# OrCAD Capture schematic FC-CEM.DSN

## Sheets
1 INDEX: title: INDEX; rev: 1.0; note: 8000084000
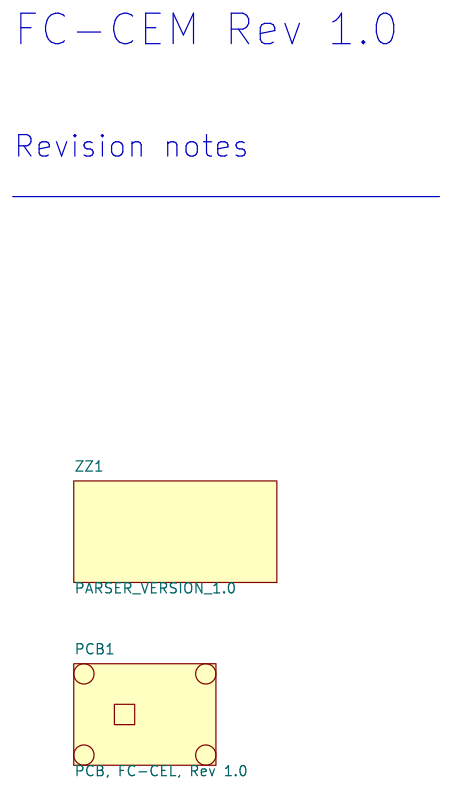
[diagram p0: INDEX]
2 M.2 SATA: size B; title: M.2 SATA
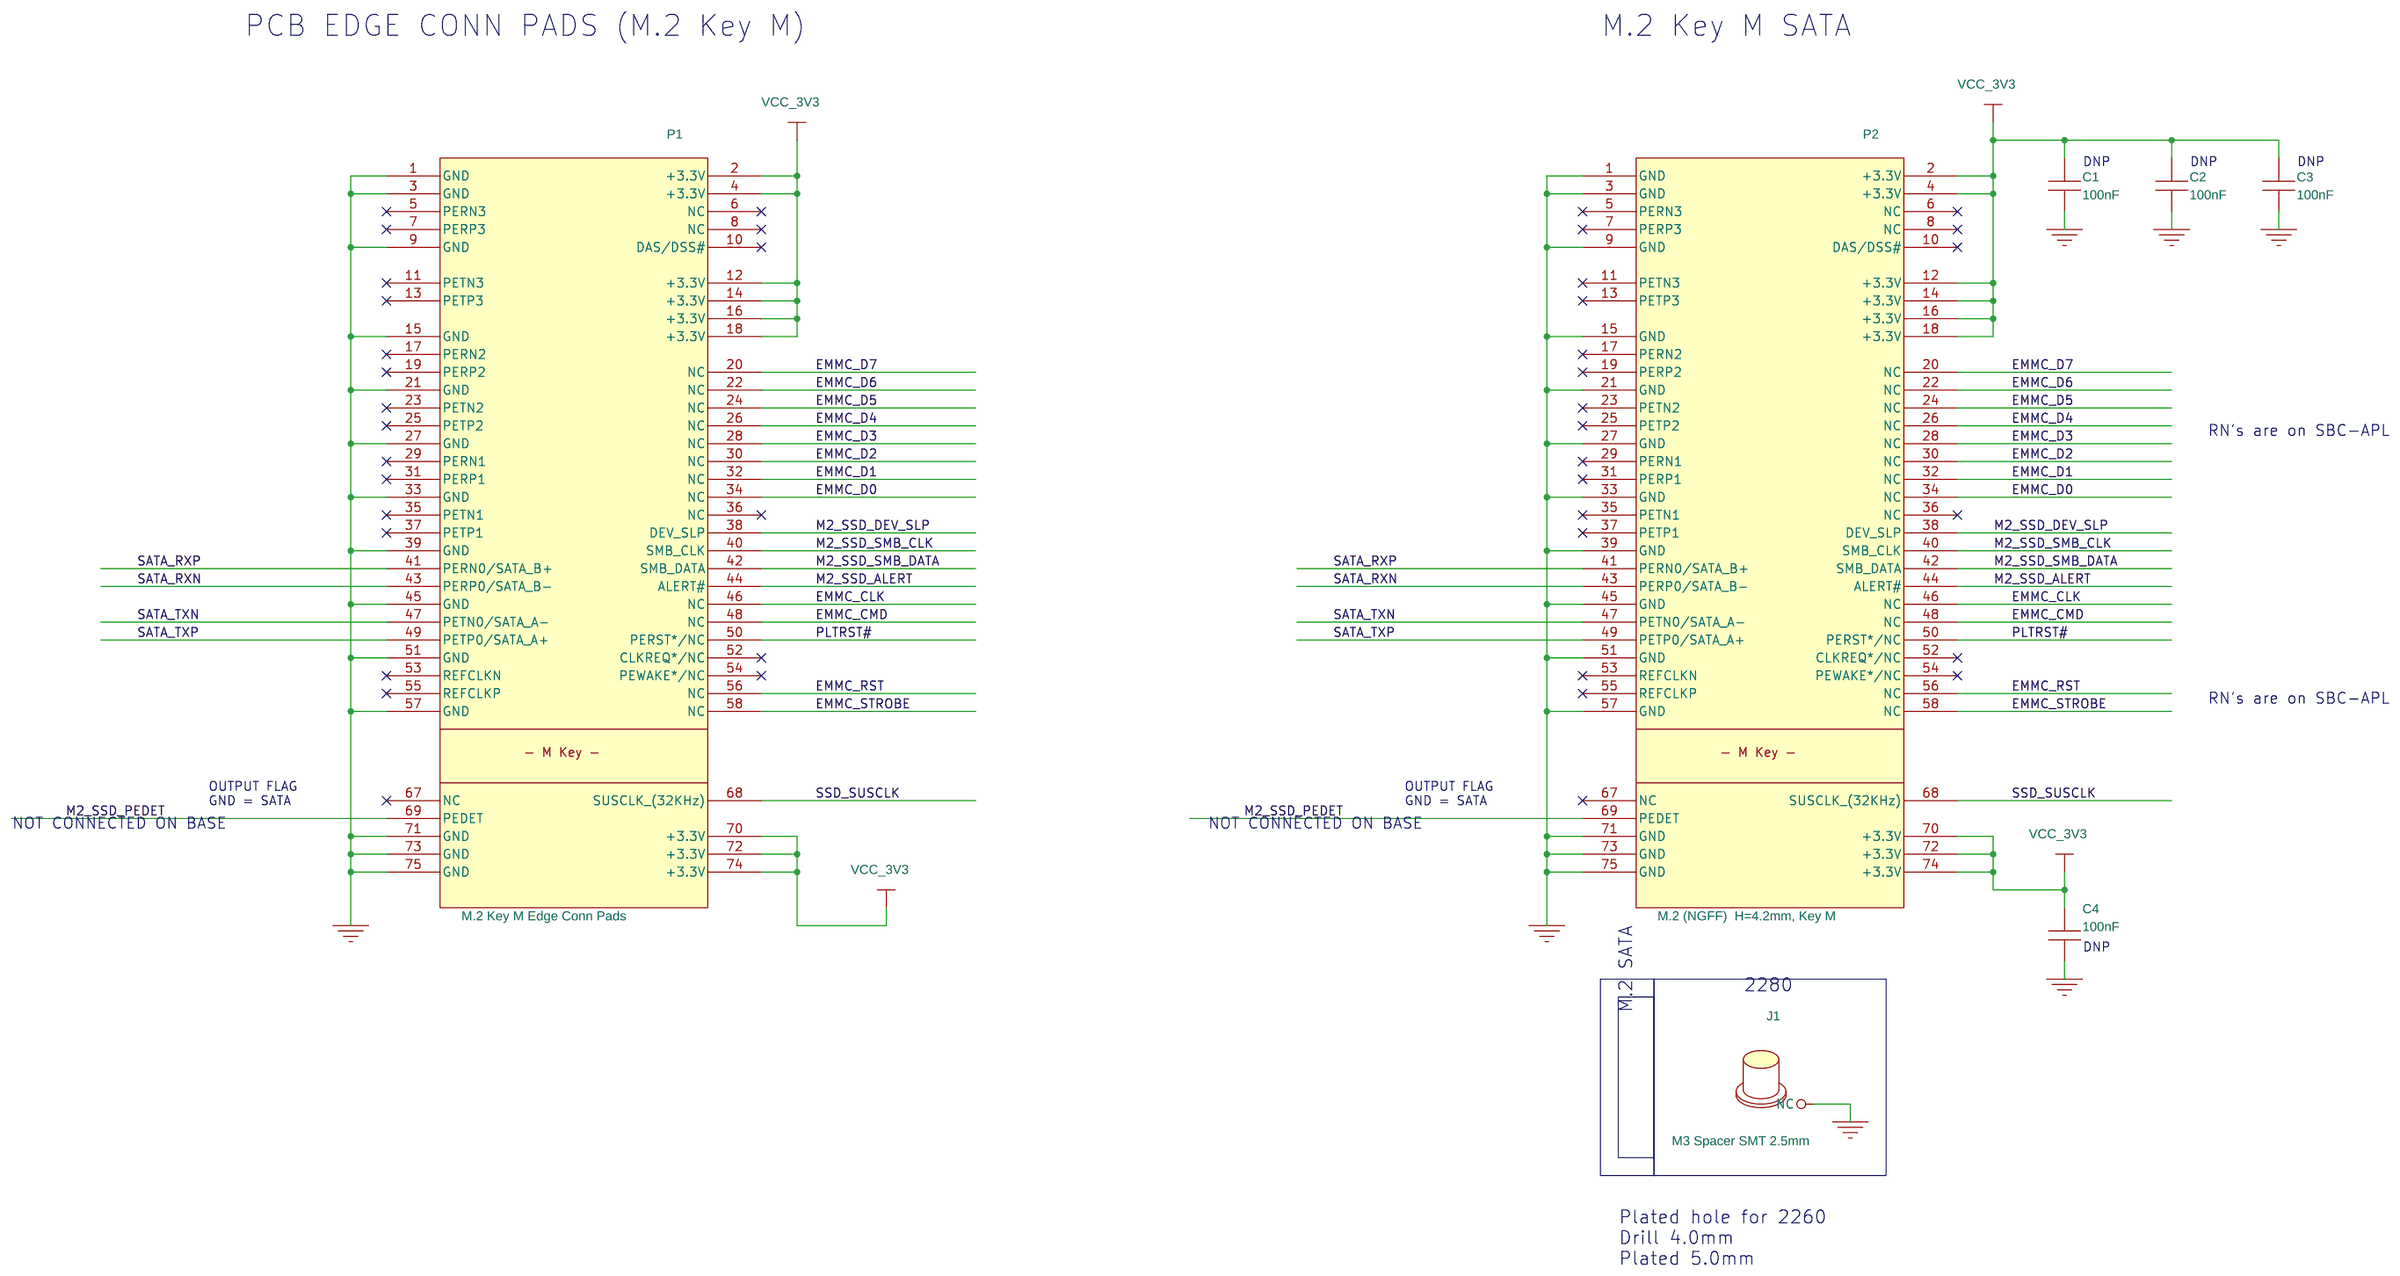
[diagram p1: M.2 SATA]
3 M.2 WIFI+BT, CELL: size C; title: WIFI+BT, CELL
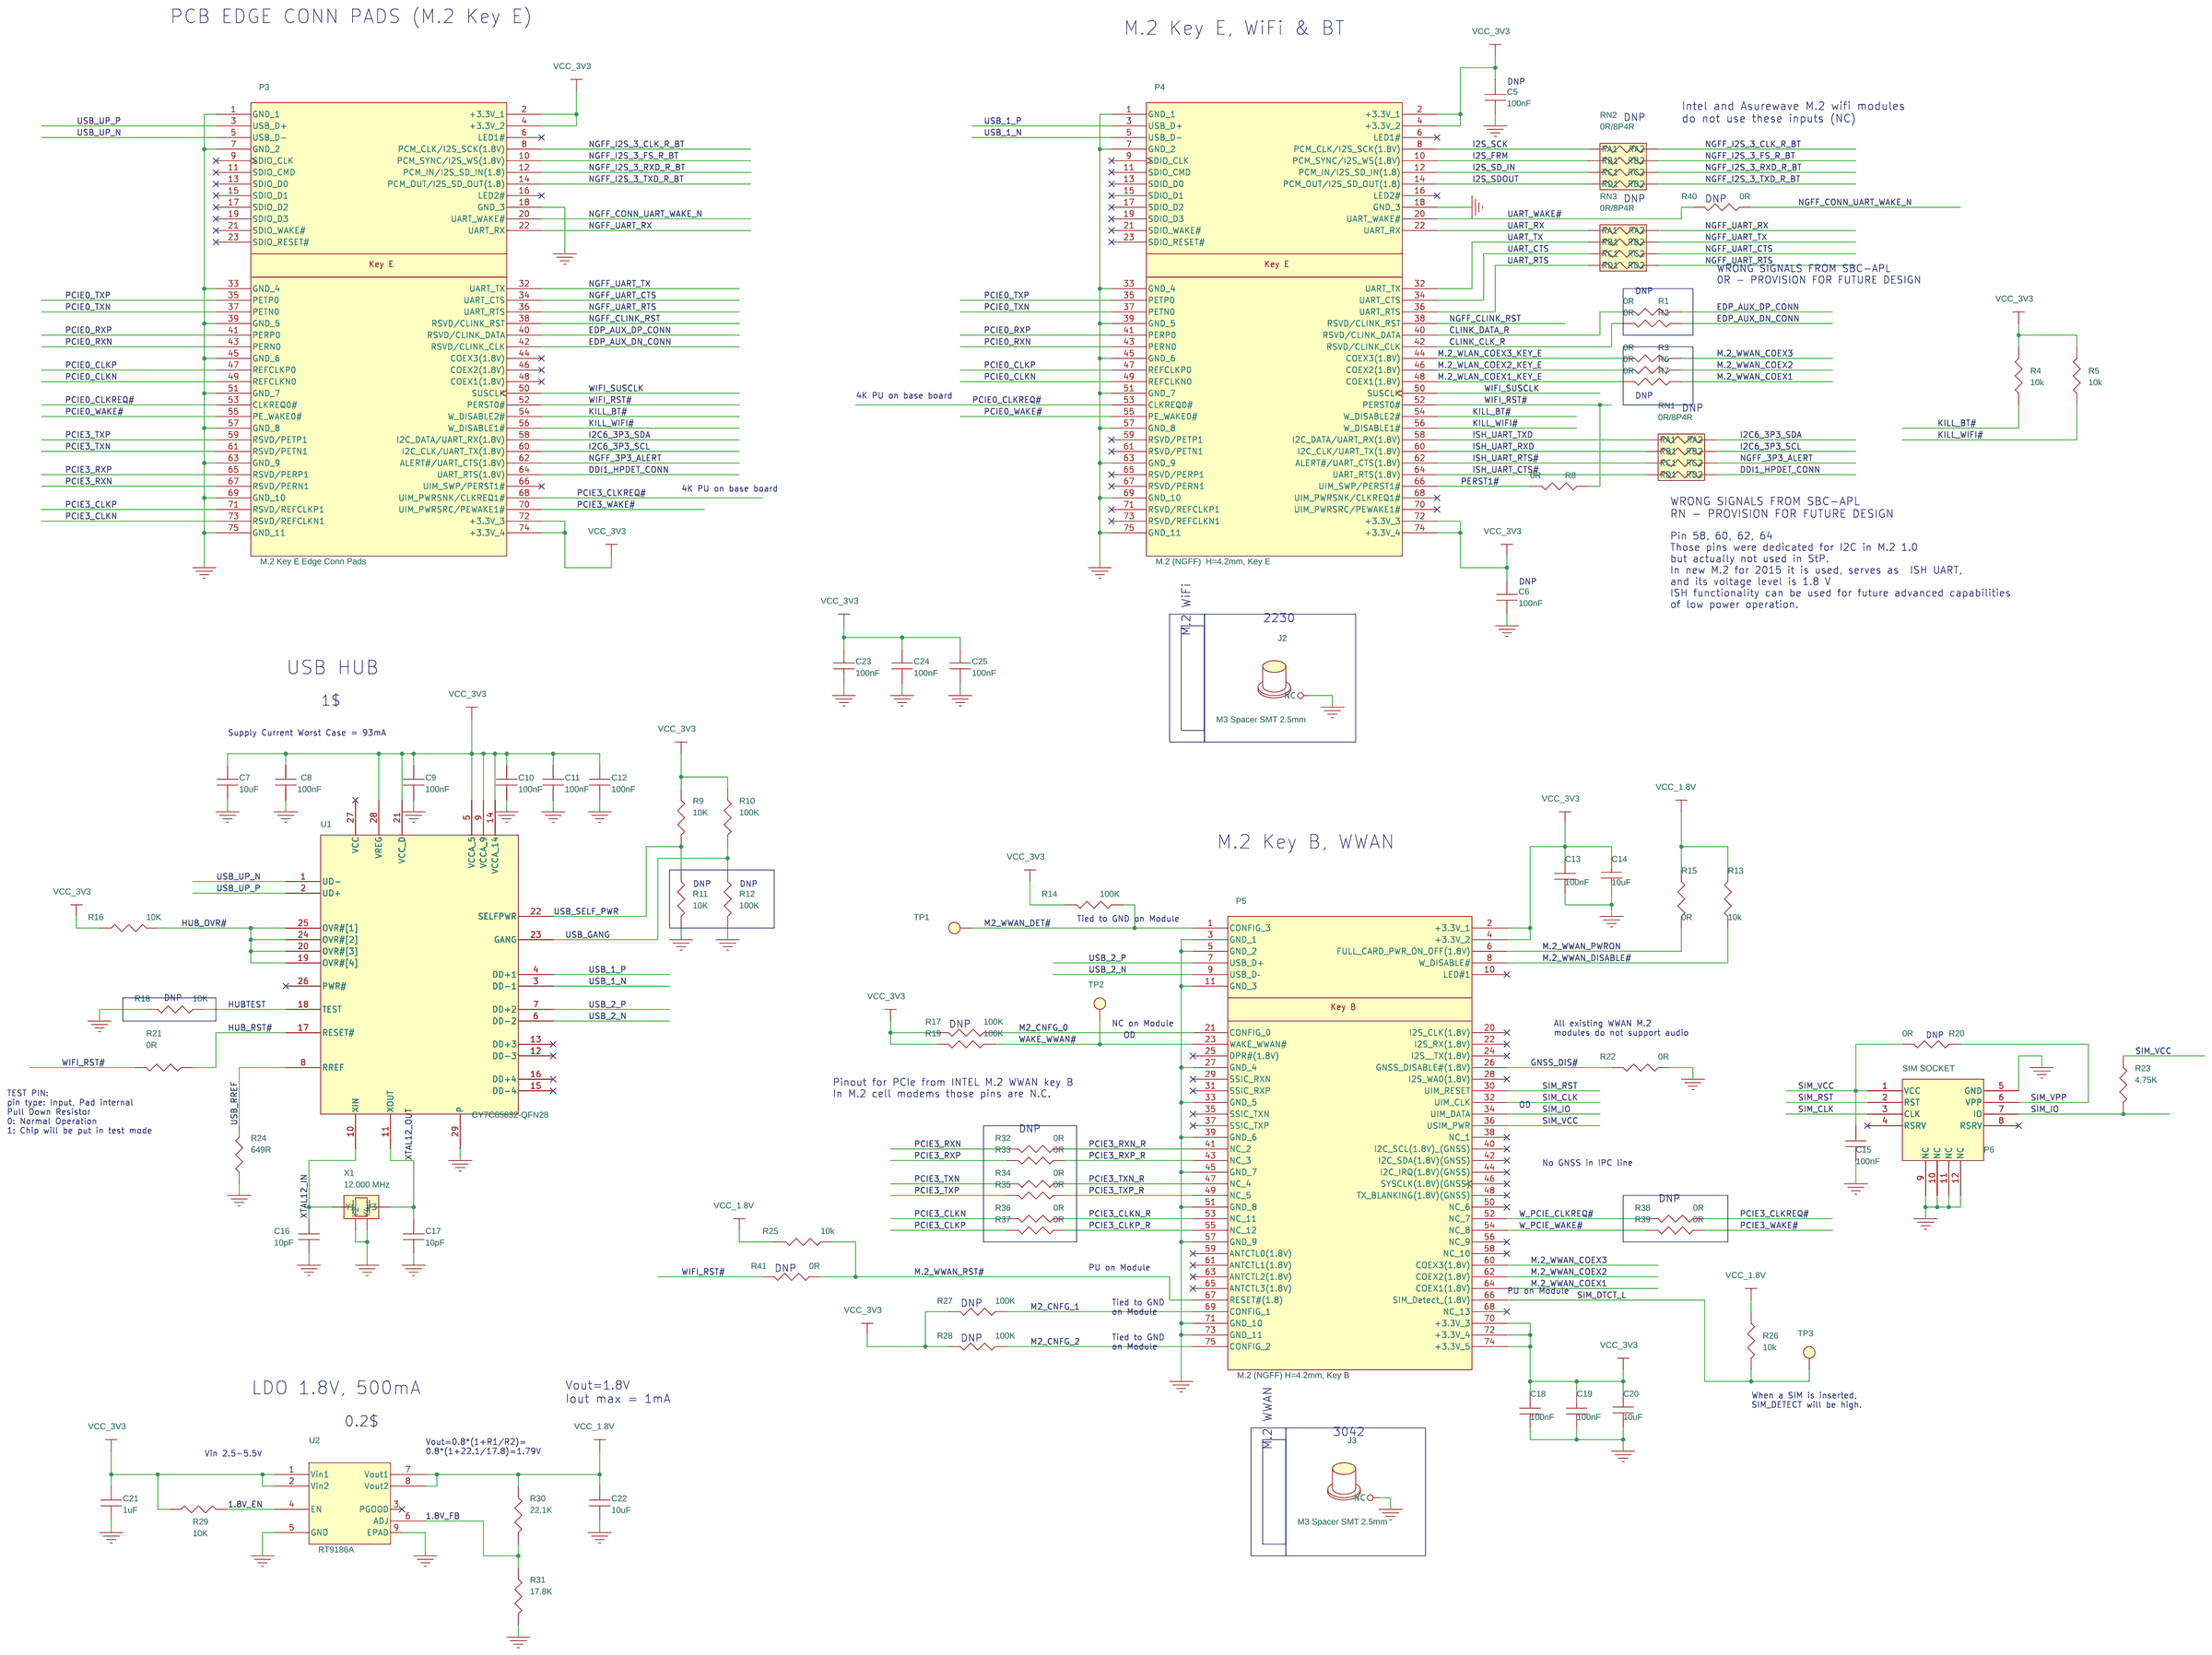
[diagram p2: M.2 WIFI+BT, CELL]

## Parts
sheet INDEX
PCB1  PCB, FC-CEL, Rev 1.0  [NA]
ZZ1  PARSER_VERSION_1.0
sheet M.2 SATA
C1  100nF  [RC0402]
C2  100nF  [RC0402]
C3  100nF  [RC0402]
C4  100nF  [RC0402]
J1  M3 Spacer SMT 2.5mm  [SpacerM3TAPSM]
P1  M.2 Key M Edge Conn Pads  [EdgeM2keyM]
P2  M.2 (NGFF)  H=4.2mm, Key M  [NGFF67P4HMkeySM]
sheet M.2 WIFI+BT, CELL
C5  100nF  [RC0402]
C6  100nF  [RC0402]
C7  10uF  [C0603-08]
C8  100nF  [RC0402]
C9  100nF  [RC0402]
C10  100nF  [RC0402]
C11  100nF  [RC0402]
C12  100nF  [RC0402]
C13  100nF  [RC0402]
C14  10uF  [RC0603]
C15  100nF  [RC0402]
C16  10pF  [RC0402]
C17  10pF  [RC0402]
C18  100nF  [RC0402]
C19  100nF  [RC0402]
C20  10uF  [RC0603]
C21  1uF  [RC0402]
C22  10uF  [C0603-08]
C23  100nF  [RC0402]
C24  100nF  [RC0402]
C25  100nF  [RC0402]
J2  M3 Spacer SMT 2.5mm  [SpacerM3TAPSM]
J3  M3 Spacer SMT 2.5mm  [SpacerM3TAPSM]
P3  M.2 Key E Edge Conn Pads  [EdgeM2keyE]
P4  M.2 (NGFF)  H=4.2mm, Key E  [NGFF67P4HEkeySM]
P5  M.2 (NGFF) H=4.2mm, Key B  [NGFF67P4HBkeySM]
P6  SIM SOCKET  [SKT-MicroSIM6-SM]
R1  0R  [RC0402]
R2  0R  [RC0402]
R3  0R  [RC0402]
R4  10k  [RC0402]
R5  10k  [RC0402]
R6  0R  [RC0402]
R7  0R  [RC0402]
R8  0R  [RC0402]
R9  10K  [RC0402]
R10  100K  [RC0402]
R11  10K  [RC0402]
R12  100K  [RC0402]
R13  10k  [RC0402]
R14  100K  [RC0402]
R15  0R  [RC0402]
R16  10K  [RC0402]
R17  100K  [RC0402]
R18  10K  [RC0402]
R19  100K  [RC0402]
R20  0R  [RC0402]
R21  0R  [RC0402]
R22  0R  [RC0402]
R23  4.75K  [RC0402]
R24  649R  [RC0402]
R25  10k  [RC0402]
R26  10k  [RC0402]
R27  100K  [RC0402]
R28  100K  [RC0402]
R29  10K  [RC0402]
R30  22.1K  [RC0402]
R31  17.8K  [RC0402]
R32  0R  [RC0402]
R33  0R  [RC0402]
R34  0R  [RC0402]
R35  0R  [RC0402]
R36  0R  [RC0402]
R37  0R  [RC0402]
R38  0R  [RC0402]
R39  0R  [RC0402]
R40  0R  [RC0402]
R41  0R  [RC0402]
RN1  0R/8P4R  [RESNET8P0805]
RN2  0R/8P4R  [RESNET8P0805]
RN3  0R/8P4R  [RESNET8P0805]
TP1  TP_VIA  [TP_SMT]
TP2  TP_VIA  [TP_SMT]
TP3  TP_VIA  [TP_SMT]
U1  CY7C65632-QFN28  [MO-220VHHD-1]
U2  RT9186A  [DFN3x3-8]
X1  12.000 MHz  [OSC3225]

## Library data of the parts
PCB1 = SBC-iPC3_rev1.1: CLABCONF0: =FC-CEM; P/N: 188C03110
ZZ1 = PARSER_VERSION_1.0
C1-C6 = 100nF_0402_25V_0: CLABCONF0: =DNP
J1-J3 = Spacer_SMT,_M2,_4mm: CLABCONF0: =FC-CEM; P/N: 383B54510S
P1 = Conn.,_M_0.2_Key_M_SATA_PCIex4: CLABCONF0: =FC-CEM; P/N: NA1
P2 = Conn.,_M_0.2_Key_M_SATA_PCIex4: CLABCONF0: =FC-CEM; P/N: 182K06700S
C7 C22 = 10uF,6.3V,0603,20%,X5R_0: CLABCONF0: =FC-CEM
C8-C12 C23-C25 = 100nF,_10V,_X7R,_10%,_0402_1: CLABCONF0: =FC-CEM
C13 C15 C18 C19 = 100nF_0402_25V_0: CLABCONF0: =FC-CEM
C14 C20 = 10uF,16V,0603,20%X5R_0: CLABCONF0: =FC-CEM
C16 C17 = 10pF,50V,NPO,_5%,_0402_0: CLABCONF0: =FC-CEM
C21 = 1uF,X5R,6.3V,0402: CLABCONF0: =FC-CEM
P3 = Conn.,_M.2_Key_E_PCIe: CLABCONF0: =FC-CEM; P/N: NA2
P4 = Conn.,_M.2_Key_E_PCIe: CLABCONF0: =FC-CEM; P/N: 182K06701S
P5 = Conn.,_M.2_Key_B_WWAN: CLABCONF0: =FC-CEM; P/N: 182K06702S
P6 = Socket,_uSim,_SMT,_6P2pin: CLABCONF0: =FC-CEM
R1-R3 R6 R7 R20 R32-R41 = 0R_0: CLABCONF0: =DNP
R4 R5 R13 R25 R26 = 1M_,5%,_0402_0: CLABCONF0: =FC-CEM; P/N: 161C10021S
R8 R15 R21 R22 = 0R_0: CLABCONF0: =FC-CEM
R9 R16 = 10K,1%,0402,1_16W_0: CLABCONF0: =FC-CEM
R10 = 100K,_0402: CLABCONF0: =FC-CEM; P/N: 161C10031S
R11 R18 = 10K,1%,0402,1_16W_0: CLABCONF0: =DNP
R12 = 100K,_0402: CLABCONF0: =DNP; P/N: 161C10031S
R14 R19 = 100K,_1%,_0402,_1_16W_0: CLABCONF0: =FC-CEM
R17 R27 R28 = 100K,_1%,_0402,_1_16W_0: CLABCONF0: =DNP
R23 = 1M_,5%,_0402_0: CLABCONF0: =FC-CEM; P/N: 161C47511S
R24 = 649R,1%,0402,1_16W: CLABCONF0: =FC-CEM
R29 = 10K,1%,0402,1_16W_0: CLABCONF0: =FC-CEM; Group: Always
R30 = 10K,1%,0402,1_16W_0: CLABCONF0: =FC-CEM; Group: Always; P/N: 161C22121S
R31 = 10K,1%,0402,1_16W_0: CLABCONF0: =FC-CEM; Group: Always; P/N: 161C17821S
RN1-RN3 = RN,0R,8P4R@0805: CLABCONF0: =DNP
TP1-TP3 = T_POINT_R
U1 = CY7C65632_X1: CLABCONF0: =FC-CEM
U2 = RT9186A,LDO_,2.5-5_0.5V,500mA: CLABCONF0: =FC-CEM
X1 = XTAL_25Mhz: CLABCONF0: =FC-CEM

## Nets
1.8V_EN: R29.2 U2.4(EN)
1.8V_FB: R30.2 R31.1 U2.6(ADJ)
GND: C1.1 C2.1 C3.1 C4.1 C5.1 C6.1 C7.2 C8.2 C9.2 C10.2 C11.2 C12.2 C13.1 C14.2 C15.1 C16.1 C17.1 C18.1 C19.1 C20.2 C21.2 C22.2 C23.2 C24.2 C25.2 J1.NC J2.NC J3.NC P1.1(GND) P1.3(GND) P1.9(GND) P1.15(GND) P1.21(GND) P1.27(GND) P1.33(GND) P1.39(GND) P1.45(GND) P1.51(GND) P1.57(GND) P1.71(GND) P1.73(GND) P1.75(GND) P2.1(GND) P2.3(GND) P2.9(GND) P2.15(GND) P2.21(GND) P2.27(GND) P2.33(GND) P2.39(GND) P2.45(GND) P2.51(GND) P2.57(GND) P2.71(GND) P2.73(GND) P2.75(GND) P3.1(GND) P3.7(GND_2) P3.18(GND_3) P3.33(GND_4) P3.39(GND_5) P3.45(GND_6) P3.51(GND_7) P3.57(GND_8) P3.63(GND_9) P3.69(GND_10) P3.75(GND_11) P4.1(GND) P4.7(GND_2) P4.18(GND_3) P4.33(GND_4) P4.39(GND_5) P4.45(GND_6) P4.51(GND_7) P4.57(GND_8) P4.63(GND_9) P4.69(GND_10) P4.75(GND_11) P5.3(GND_1) P5.5(GND_2) P5.11(GND_3) P5.27(GND_4) P5.33(GND_5) P5.39(GND_6) P5.45(GND_7) P5.51(GND_8) P5.57(GND_9) P5.71(GND_10) P5.73(GND_11) P6.5(GND) P6.9(NC) P6.10(NC) P6.11(NC) P6.12(NC) R11.2 R12.2 R18.2 R22.1 R24.1 R31.2 U1.29(P) U2.5(GND) U2.9(EPAD) X1.2(Y2) X1.4(Y4)
VCC_1.8V: C22.1 R13.2 R15.1 R25.2 R26.1 R30.1 U2.7(Vout1) U2.8(Vout2)
VCC_3V3: C1.2 C2.2 C3.2 C4.2 C5.2 C6.2 C7.1 C8.1 C9.1 C10.1 C11.1 C12.1 C13.2 C14.1 C18.2 C19.2 C20.1 C21.1 C23.1 C24.1 C25.1 P1.2(+3.3V) P1.4(+3.3V) P1.12(+3.3V) P1.14(+3.3V) P1.16(+3.3V) P1.18(+3.3V) P1.70(+3.3V) P1.72(+3.3V) P1.74(+3.3V) P2.2(+3.3V) P2.4(+3.3V) P2.12(+3.3V) P2.14(+3.3V) P2.16(+3.3V) P2.18(+3.3V) P2.70(+3.3V) P2.72(+3.3V) P2.74(+3.3V) P3.2(+3.3V_1) P3.4(+3.3V_2) P3.72(+3.3V_3) P3.74(+3.3V_4) P4.2(+3.3V_1) P4.4(+3.3V_2) P4.72(+3.3V_3) P4.74(+3.3V_4) P5.2(+3.3V_1) P5.4(+3.3V_2) P5.70(+3.3V_3) P5.72(+3.3V_4) P5.74(+3.3V_5) R4.2 R5.2 R9.1 R10.1 R14.2 R16.1 R17.2 R19.2 R27.2 R28.2 R29.1 U1.5(VCCA) U1.9(VCCA) U1.14(VCCA) U1.21(VCC_D) U1.28(VREG) U2.1(Vin1) U2.2(Vin2)
CLINK_CLK_R: P4.42(RSVD/CLINK_CLK) R2.2
CLINK_DATA_R: P4.40(RSVD/CLINK_DATA) R1.2
DDI1_HPDET_CONN: P3.64(UART_RTS(1.8V)) RN1.5(RD2)
EDP_AUX_DN_CONN: P3.42(RSVD/CLINK_CLK) R2.1
EDP_AUX_DP_CONN: P3.40(RSVD/CLINK_DATA) R1.1
EMMC_CLK: P1.46(NC) P2.46(NC)
EMMC_CMD: P1.48(NC) P2.48(NC)
EMMC_D0: P1.34(NC) P2.34(NC)
EMMC_D1: P1.32(NC) P2.32(NC)
EMMC_D2: P1.30(NC) P2.30(NC)
EMMC_D3: P1.28(NC) P2.28(NC)
EMMC_D4: P1.26(NC) P2.26(NC)
EMMC_D5: P1.24(NC) P2.24(NC)
EMMC_D6: P1.22(NC) P2.22(NC)
EMMC_D7: P1.20(NC) P2.20(NC)
EMMC_RST: P1.56(NC) P2.56(NC)
EMMC_STROBE: P1.58(NC) P2.58(NC)
GNSS_DIS#: P5.26(GNSS_DISABLE#(1.8V)) R22.2
HUB_OVR#: R16.2 U1.19(OVR#[4]) U1.20(OVR#[3]) U1.24(OVR#[2]) U1.25(OVR#[1])
HUB_RST#: R21.1 U1.17(RESET#)
HUBTEST: R18.1 U1.18(TEST)
I2C6_3P3_SCL: P3.60(I2C_CLK/UART_TX(1.8V)) RN1.7(RB2)
I2C6_3P3_SDA: P3.58(I2C_DATA/UART_RX(1.8V)) RN1.8(RA2)
I2S_FRM: P4.10(PCM_SYNC/I2S_WS(1.8V)) RN2.2(RB1)
I2S_SCK: P4.8(PCM_CLK/I2S_SCK(1.8V)) RN2.1(RA1)
I2S_SD_IN: P4.12(PCM_IN/I2S_SD_IN(1.8)) RN2.3(RC1)
I2S_SDOUT: P4.14(PCM_OUT/I2S_SD_OUT(1.8)) RN2.4(RD1)
ISH_UART_CTS#: P4.64(UART_RTS(1.8V)) RN1.4(RD1)
ISH_UART_RTS#: P4.62(ALERT#/UART_CTS(1.8V)) RN1.3(RC1)
ISH_UART_RXD: P4.60(I2C_CLK/UART_TX(1.8V)) RN1.2(RB1)
ISH_UART_TXD: P4.58(I2C_DATA/UART_RX(1.8V)) RN1.1(RA1)
KILL_BT#: P3.54(W_DISABLE2#) P4.54(W_DISABLE2#) R4.1
KILL_WIFI#: P3.56(W_DISABLE1#) P4.56(W_DISABLE1#) R5.1
M2_CNFG_0: P5.21(CONFIG_0) R17.1
M2_CNFG_1: P5.69(CONFIG_1) R27.1
M2_CNFG_2: P5.75(CONFIG_2) R28.1
M2_SSD_ALERT: P1.44(ALERT#) P2.44(ALERT#)
M2_SSD_DEV_SLP: P1.38(DEV_SLP) P2.38(DEV_SLP)
M2_SSD_PEDET: P1.69(PEDET) P2.69(PEDET)
M2_SSD_SMB_CLK: P1.40(SMB_CLK) P2.40(SMB_CLK)
M2_SSD_SMB_DATA: P1.42(SMB_DATA) P2.42(SMB_DATA)
M2_WWAN_DET#: P5.1(CONFIG_3) R14.1 TP1.1(TP)
M.2_WLAN_COEX1_KEY_E: P4.48(COEX1(1.8V)) R7.2
M.2_WLAN_COEX2_KEY_E: P4.46(COEX2(1.8V)) R6.2
M.2_WLAN_COEX3_KEY_E: P4.44(COEX3(1.8V)) R3.2
M.2_WWAN_COEX1: P5.64(COEX1(1.8V)) R7.1
M.2_WWAN_COEX2: P5.62(COEX2(1.8V)) R6.1
M.2_WWAN_COEX3: P5.60(COEX3(1.8V)) R3.1
M.2_WWAN_DISABLE#: P5.8(W_DISABLE#) R13.1
M.2_WWAN_PWRON: P5.6(FULL_CARD_PWR_ON_OFF(1.8V)) R15.2
M.2_WWAN_RST#: P5.67(RESET#(1.8)) R25.1 R41.1
NGFF_3P3_ALERT: P3.62(ALERT#/UART_CTS(1.8V)) RN1.6(RC2)
NGFF_CLINK_RST: P3.38(RSVD/CLINK_RST) P4.38(RSVD/CLINK_RST)
NGFF_CONN_UART_WAKE_N: P3.20(UART_WAKE#) R40.1
NGFF_I2S_3_CLK_R_BT: P3.8(PCM_CLK/I2S_SCK(1.8V)) RN2.8(RA2)
NGFF_I2S_3_FS_R_BT: P3.10(PCM_SYNC/I2S_WS(1.8V)) RN2.7(RB2)
NGFF_I2S_3_RXD_R_BT : P3.12(PCM_IN/I2S_SD_IN(1.8)) RN2.6(RC2)
NGFF_I2S_3_TXD_R_BT: P3.14(PCM_OUT/I2S_SD_OUT(1.8)) RN2.5(RD2)
NGFF_UART_CTS: P3.34(UART_CTS) RN3.6(RC2)
NGFF_UART_RTS: P3.36(UART_RTS) RN3.5(RD2)
NGFF_UART_RX: P3.22(UART_RX) RN3.8(RA2)
NGFF_UART_TX: P3.32(UART_TX) RN3.7(RB2)
PCIE0_CLKN: P3.49(REFCLKN0) P4.49(REFCLKN0)
PCIE0_CLKP: P3.47(REFCLKP0) P4.47(REFCLKP0)
PCIE0_CLKREQ#: P3.53(CLKREQ0#) P4.53(CLKREQ0#)
PCIE0_RXN: P3.43(PERN0) P4.43(PERN0)
PCIE0_RXP: P3.41(PERP0) P4.41(PERP0)
PCIE0_TXN: P3.37(PETN0) P4.37(PETN0)
PCIE0_TXP: P3.35(PETP0) P4.35(PETP0)
PCIE0_WAKE#: P3.55(PE_WAKE0#) P4.55(PE_WAKE0#)
PCIE3_CLKN: P3.73(RSVD/REFCLKN1) R36.2
PCIE3_CLKN_R: P5.53(NC_11) R36.1
PCIE3_CLKP: P3.71(RSVD/REFCLKP1) R37.2
PCIE3_CLKP_R: P5.55(NC_12) R37.1
PCIE3_CLKREQ#: P3.68(UIM_PWRSNK/CLKREQ1#) R38.1
PCIE3_RXN: P3.67(RSVD/PERN1) R32.2
PCIE3_RXN_R: P5.41(NC_2) R32.1
PCIE3_RXP: P3.65(RSVD/PERP1) R33.2
PCIE3_RXP_R: P5.43(NC_3) R33.1
PCIE3_TXN: P3.61(RSVD/PETN1) R34.2
PCIE3_TXN_R: P5.47(NC_4) R34.1
PCIE3_TXP: P3.59(RSVD/PETP1) R35.2
PCIE3_TXP_R: P5.49(NC_5) R35.1
PCIE3_WAKE#: P3.70(UIM_PWRSRC/PEWAKE1#) R39.1
PERST1#: P4.66(UIM_SWP/PERST1#) R8.2
PLTRST#: P1.50(PERST*/NC) P2.50(PERST*/NC)
SATA_RXN: P1.43(PERP0/SATA_B-) P2.43(PERP0/SATA_B-)
SATA_RXP: P1.41(PERN0/SATA_B+) P2.41(PERN0/SATA_B+)
SATA_TXN: P1.47(PETN0/SATA_A-) P2.47(PETN0/SATA_A-)
SATA_TXP: P1.49(PETP0/SATA_A+) P2.49(PETP0/SATA_A+)
SIM_CLK: P5.32(UIM_CLK) P6.3(CLK)
SIM_DTCT_L: P5.66(SIM_Detect_(1.8V)) R26.2 TP3.1(TP)
SIM_IO: P5.34(UIM_DATA) P6.7(IO) R23.2
SIM_RST: P5.30(UIM_RESET) P6.2(RST)
SIM_VCC: C15.2 P5.36(USIM_PWR) P6.1(VCC) R20.2 R23.1
SIM_VPP: P6.6(VPP) R20.1
SSD_SUSCLK: P1.68(SUSCLK_(32KHz)) P2.68(SUSCLK_(32KHz))
UART_CTS: P4.34(UART_CTS) RN3.3(RC1)
UART_RTS: P4.36(UART_RTS) RN3.4(RD1)
UART_RX: P4.22(UART_RX) RN3.1(RA1)
UART_TX: P4.32(UART_TX) RN3.2(RB1)
UART_WAKE#: P4.20(UART_WAKE#) R40.2
USB_1_N: P4.5(USB_D-) U1.3(DD-1)
USB_1_P: P4.3(USB_D+) U1.4(DD+1)
USB_2_N: P5.9(USB_D–) U1.6(DD-2)
USB_2_P: P5.7(USB_D+) U1.7(DD+2)
USB_GANG: R10.2 R12.1 U1.23(GANG)
USB_RREF: R24.2 U1.8(RREF)
USB_SELF_PWR: R9.2 R11.1 U1.22(SELFPWR)
USB_UP_N: P3.5(USB_D-) U1.1(UD-)
USB_UP_P: P3.3(USB_D+) U1.2(UD+)
W_PCIE_CLKREQ#: P5.52(NC_7) R38.2
W_PCIE_WAKE#: P5.54(NC_8) R39.2
WAKE_WWAN#: P5.23(WAKE_WWAN#) R19.1 TP2.1(TP)
WIFI_RST#: P3.52(PERST0#) P4.52(PERST0#) R8.1 R21.2 R41.2
WIFI_SUSCLK: P3.50(SUSCLK) P4.50(SUSCLK)
XTAL12_IN: C16.2 U1.10(XIN) X1.1(Y1)
XTAL12_OUT: C17.2 U1.11(XOUT) X1.3(Y3)

Not connected (* = marked no-connect by the designer): P1 5(PERN3)* 6(NC)* 7(PERP3)* 8(NC)* 10(DAS/DSS#)* 11(PETN3)* 13(PETP3)* 17(PERN2)* 19(PERP2)* 23(PETN2)* 25(PETP2)* 29(PERN1)* 31(PERP1)* 35(PETN1)* 36(NC)* 37(PETP1)* 52(CLKREQ*/NC)* 53(REFCLKN)* 54(PEWAKE*/NC)* 55(REFCLKP)* 67(NC)*; P2 5(PERN3)* 6(NC)* 7(PERP3)* 8(NC)* 10(DAS/DSS#)* 11(PETN3)* 13(PETP3)* 17(PERN2)* 19(PERP2)* 23(PETN2)* 25(PETP2)* 29(PERN1)* 31(PERP1)* 35(PETN1)* 36(NC)* 37(PETP1)* 52(CLKREQ*/NC)* 53(REFCLKN)* 54(PEWAKE*/NC)* 55(REFCLKP)* 67(NC)*; P3 6(LED1#)* 9(SDIO_CLK)* 11(SDIO_CMD)* 13(SDIO_D0)* 15(SDIO_D1)* 16(LED2#)* 17(SDIO_D2)* 19(SDIO_D3)* 21(SDIO_WAKE#)* 23(SDIO_RESET#)* 44(COEX3(1.8V))* 46(COEX2(1.8V))* 48(COEX1(1.8V))* 66(UIM_SWP/PERST1#)*; P4 6(LED1#)* 9(SDIO_CLK)* 11(SDIO_CMD)* 13(SDIO_D0)* 15(SDIO_D1)* 16(LED2#)* 17(SDIO_D2)* 19(SDIO_D3)* 21(SDIO_WAKE#)* 23(SDIO_RESET#)* 59(RSVD/PETP1)* 61(RSVD/PETN1)* 65(RSVD/PERP1)* 67(RSVD/PERN1)* 68(UIM_PWRSNK/CLKREQ1#)* 70(UIM_PWRSRC/PEWAKE1#)* 71(RSVD/REFCLKP1)* 73(RSVD/REFCLKN1)*; P5 10(LED#1)* 20(I2S_CLK(1.8V))* 22(I2S_RX(1.8V))* 24(I2S__TX(1.8V))* 25(DPR#(1.8V))* 28(I2S_WA0(1.8V))* 29(SSIC_RXN)* 31(SSIC_RXP)* 35(SSIC_TXN)* 37(SSIC_TXP)* 38(NC_1)* 40(I2C_SCL(1.8V)_(GNSS))* 42(I2C_SDA(1.8V)(GNSS))* 44(I2C_IRQ(1.8V)(GNSS))* 46(SYSCLK(1.8V)(GNSS))* 48(TX_BLANKING(1.8V)(GNSS))* 50(NC_6)* 56(NC_9)* 58(NC_10)* 59(ANTCTL0(1.8V))* 61(ANTCTL1(1.8V))* 63(ANTCTL2(1.8V))* 65(ANTCTL3(1.8V))* 68(NC_13)*; P6 4(RSRV)* 8(RSRV)*; U1 12(DD-3)* 13(DD+3)* 15(DD-4)* 16(DD+4)* 26(PWR#)* 27(VCC)*; U2 3(PGOOD)*

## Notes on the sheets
sheet 1
- FC-CEM Rev 1.0
- Revision notes
sheet 2
- PCB EDGE CONN PADS (M.2 Key M)
- M.2 Key M SATA
- DNP
- DNP
- DNP
- RN's are on SBC-APL
- RN's are on SBC-APL
- OUTPUT FLAG
  GND = SATA
- OUTPUT FLAG
  GND = SATA
- NOT CONNECTED ON BASE
- NOT CONNECTED ON BASE
- DNP
- 2280
- M.2 SATA
- Plated hole for 2260
  Drill 4.0mm
  Plated 5.0mm
sheet 3
- PCB EDGE CONN PADS (M.2 Key E)
- M.2 Key E, WiFi & BT
- DNP
- Intel and Asurewave M.2 wifi modules
  do not use these inputs (NC)
- DNP
- DNP
- DNP
- WRONG SIGNALS FROM SBC-APL
  0R - PROVISION FOR FUTURE DESIGN
- DNP
- 4K PU on base board
- DNP
- DNP
- 4K PU on base board
- WRONG SIGNALS FROM SBC-APL
  RN - PROVISION FOR FUTURE DESIGN
- Pin 58, 60, 62, 64
  Those pins were dedicated for I2C in M.2 1.0
  but actually not used in StP.
  In new M.2 for 2015 it is used, serves as  ISH UART,
  and its voltage level is 1.8 V
  ISH functionality can be used for future advanced capabilities
  of low power operation.
- DNP
- 2230
- M.2 WiFi
- USB HUB
- 1$
- Supply Current Worst Case = 93mA
- M.2 Key B, WWAN
- DNP
- DNP
- Tied to GND on Module
- DNP
- DNP
- NC on Module
- All existing WWAN M.2
  modules do not support audio
- OD
- DNP
- Pinout for PCIe from INTEL M.2 WWAN key B
  In M.2 cell modems those pins are N.C.
- TEST PIN:
  pin type: Input, Pad internal
  Pull Down Resistor
  0: Normal Operation
  1: Chip will be put in test mode
- OD
- DNP
- No GNSS in IPC line
- DNP
- DNP
- PU on Module
- PU on Module
- DNP
- Tied to GND
  on Module
- DNP
- Tied to GND
  on Module
- LDO 1.8V, 500mA
- Vout=1.8V
  Iout max = 1mA
- When a SIM is inserted,
  SIM_DETECT will be high.
- 0.2$
- 3042
- Vout=0.8*(1+R1/R2)=
  0.8*(1+22.1/17.8)=1.79V
- Vin 2.5-5.5V
- M.2 WWAN
